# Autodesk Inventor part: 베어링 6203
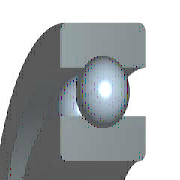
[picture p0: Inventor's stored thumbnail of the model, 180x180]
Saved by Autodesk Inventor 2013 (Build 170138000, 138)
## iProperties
IsCustomPart: 0
Created: 2014-10
Part Number: 베어링 6203
Material: 알루미늄 6061
Description: 깊은 그루브 볼 베어링
Document SubType Name: Modeling
Standard: KS B 2023
Designer: KYOUNG IL JANG
Standards Organization: KS
Language: ko-KR
Size Designation: 6203 - 17 x 40 x 12
Categories: <MemberInstance><Categories><Category DisplayName="샤프트 부품" InternalName="7f7aeb1f-a693-4053-b835-cee3144e0d98" Mnemonic="SHFT"><Category DisplayName="베어링" Inter
Density: 2.71 g/cm^3
Mass: 22.4044 g
Surface Area: 64.3582 cm^2
Volume: 8.26729 cm^3
Author: SeoGD™ [www.esajin.kr]
Revision Number: 1
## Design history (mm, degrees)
sketch "스케치" dims "d0" = 5.98 (= -0.26 x WD + 0.26 x BD)
  geometry: L1 (3.01, 14.25)-(8.99, 14.25); L2 (6, 14.25)-(6, 11.26); L3 (6, 14.25)-(6, 17.24); L4 (3.778, 12.249)-(0, 12.249); L5 (0, 8.5)-(12, 8.5); L6 (3.778, 16.251)-(0, 16.251); L7 (0, 20)-(12, 20); L8 (12, 8.5)-(12, 12.249); L9 (8.222, 12.249)-(12, 12.249); L10 (8.222, 16.251)-(12, 16.251); L11 (12, 20)-(12, 16.251); L12 (-1.4, 0)-(8.4, 0) reference; L13 (0, -0.3)-(0, 5.3) reference
  constraints: 22 end point, 4 point on line, 2 collinear, 2 perpendicular, 2 symmetric about line, 1 midpoint, 1 parallel, 14 other
  dimensions: "d9" = 17 diameter of L5 L12 (= WD); "d11" = 40 diameter of L7 L12 (= BD); "d12" = 12 distance between parallel lines of L8 L13 (= KB); "d13" = 24.498 diameter of L9 L12 (= 0.326 x BD + 0.674 x WD)
revolve "본체" stored, may be unused: angle "d6" = 90 deg
revolve "볼" stored, may be unused: angle "d7" = 90 deg
pattern_circular "IDS_ARRAYBALL[SIMPL:T]" dims angle "d3" = 360 deg
body "Solid1"
fillet "모깎기1" dims "d1" = 0.6 (= KRS)
other parameters: "WD" = 17 [user parameter; used in 5 equation terms], "BD" = 40 [user parameter; used in 5 equation terms], "KB" = 12 [user parameter; used in 1 equation term], "KRS" = 0.6 [user parameter; used in 1 equation term], "d4" = 0, "d5" = 0, "d8" = 0, "d14" = 0, "d15" = 0, "BBA" = 0 [user parameter], "BC0" = 4750000 [user parameter], "BC" = 9560000 [user parameter], "WR" = 8.5 (= 0.5 x WD) [user parameter]
